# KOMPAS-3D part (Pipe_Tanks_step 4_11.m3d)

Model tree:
1. X Axis
2. Y Axis
3. Z Axis  (labels: T-Bend Dn 150; Pipe Dn 150; Valve Dy 150)
     Òîëùèíà ñòåíêè 1 = 1

Referenced files in C:\Documents and Settings\kashirsky\Мои документы\Camtasia Studio\Pipelines3D\Tanks\: Tanks_step 4.a3d
Referenced files in C:\Program Files\ASCON\KOMPAS-3D V10\Libs\Piping\LOAD\: Piping_C_Pipe_150_1000.m3d
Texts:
  Pipe Dn 150
  Steel ASTM A295
  Three Point Plane
  Plane at Angle
  Line and Point Plane
  Axis through Two Vertices
  Axis of Feature
  Axis of Conical Surface
  Axis through Edge
  Trim by Surface
  Trim by Sketch
  Feature with No History
  Intersection Axis of Two Planes
  Two Line Plane
  Line and Face Plane
  Bend by line
  Hole in sheet body
  Cut in sheet body
  Point in CM
  Linear Dimension from Line to Point
  Surface Finish Symbol
  Geometric Tolerance Symbol
  Leader #1
  Leader #2
  Leader #3
  Shape Deviations and Datum
  Node point number
  Mark of coordination axis
  Node point designation
  Mark/Reference designation with leader
  Mark/reference designation on line
  Mark/Reference designation without leader
  T-Bend Dn 150
  Valve Dy 150
  Plane of section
